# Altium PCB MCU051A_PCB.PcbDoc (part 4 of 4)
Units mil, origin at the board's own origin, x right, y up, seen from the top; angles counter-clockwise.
Board outline 4000 x 6000 mil, 6 copper layers (Top Layer, Signal Layer 1, Signal Layer 2, Signal Layer 3, Signal Layer 4, Bottom Layer), stack 60.4 mil thick; 193 components, 239 nets, 864 pads, 621 vias.
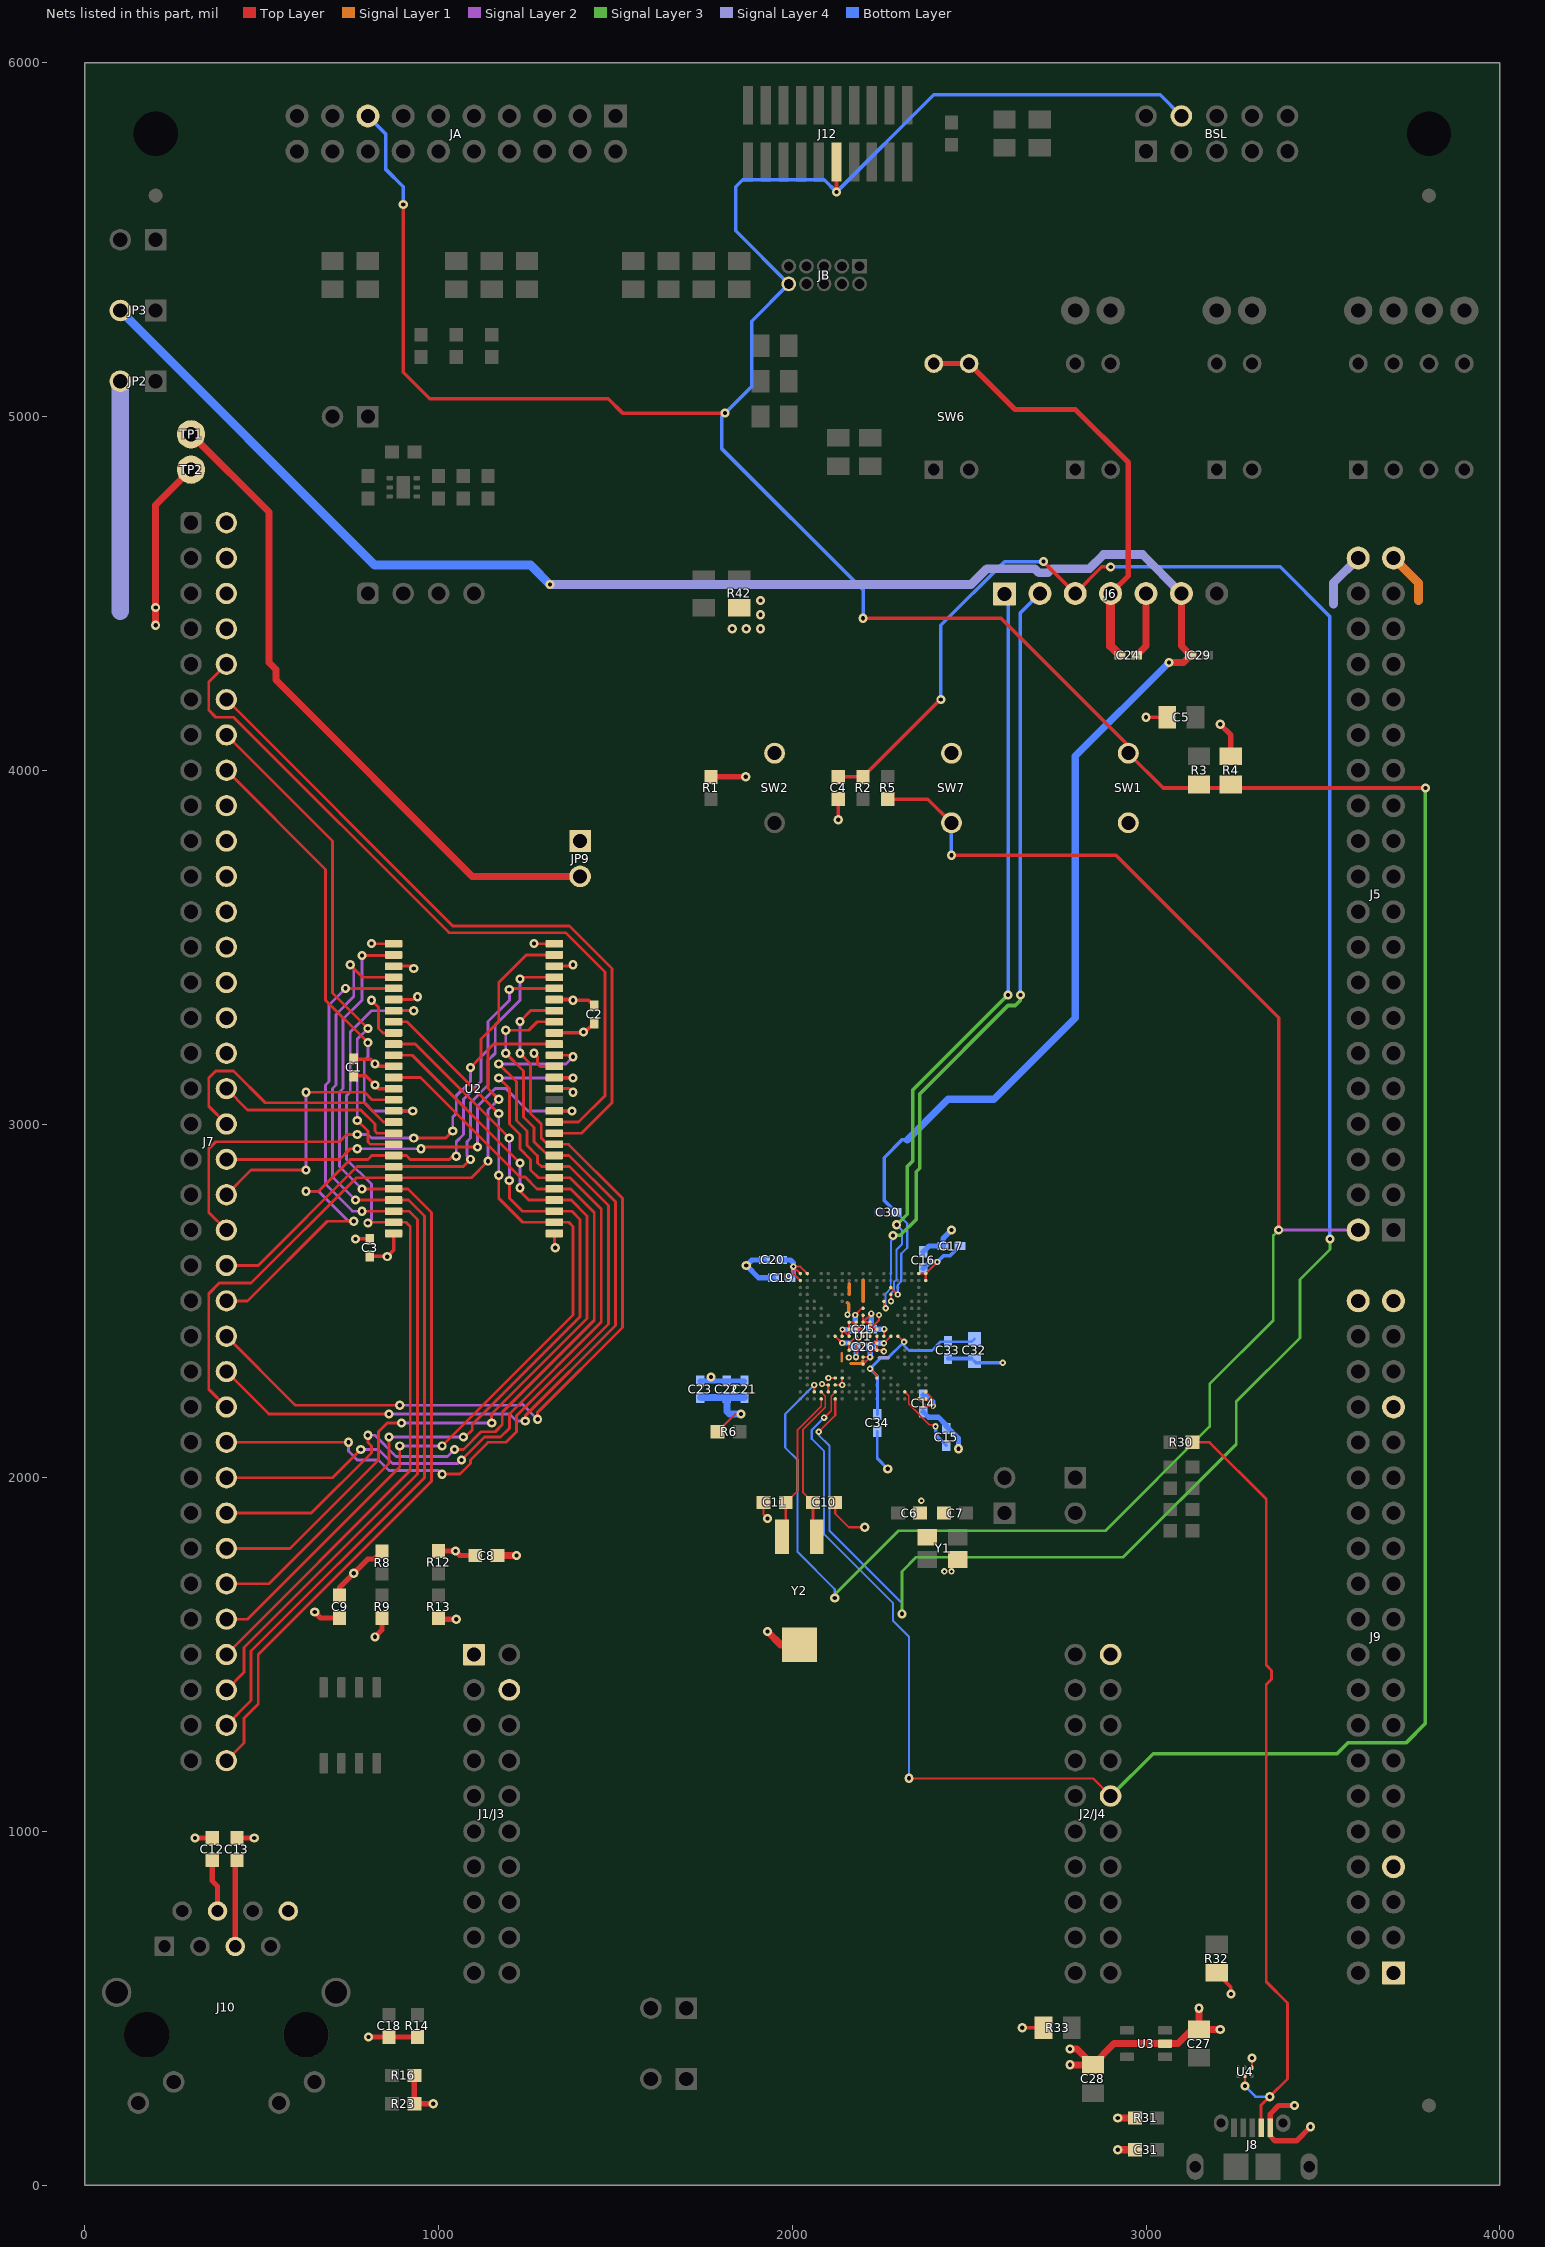
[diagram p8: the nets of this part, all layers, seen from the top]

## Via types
v1: diameter 26, hole 12, Top Layer to Bottom Layer, tented both sides, 517 vias
v2: diameter 18, hole 8, Top Layer to Bottom Layer, tented both sides, 94 vias
v3: diameter 26, hole 12, Top Layer to Bottom Layer, 7 vias
v4: diameter 19.68, hole 7.87, Top Layer to Bottom Layer, 2 vias
v5: diameter 18, hole 8, Top Layer to Bottom Layer, 1 vias

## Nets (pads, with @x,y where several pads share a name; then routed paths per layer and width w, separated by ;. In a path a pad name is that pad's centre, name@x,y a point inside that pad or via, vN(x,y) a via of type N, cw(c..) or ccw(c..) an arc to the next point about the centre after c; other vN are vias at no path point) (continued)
RSTn: BSL.4 J2/J4.16 J12.10 JA.15 JB.10 R3.1 R4.1 SW1.1 U1.P18 | length 12003
  Top Layer w4: v2(2090,2170) 2109.57,2189.57 2109.57,2230.83 U1.P18@2121.26,2242.52
  Top Layer w6: v1(2330,1150) 2850,1150 J2/J4.16@2900,1100
  Top Layer w10: v1(900,5600) 900,5125 975,5050 1480,5050 1520,5010 v1(1810,5010) ; v1(2125,5635) J12.10@2125,5719.88 ; v1(2200,4430) 2590,4430 2950,4070 SW1.1@2950,4048.43 3048.43,3950 v1(3790,3950)
  Signal Layer 3 w10: J2/J4.16@2900,1100 3020,1220 3540,1220 3570,1250 3735,1250 3790,1305 v1(3790,3950)
  Bottom Layer w6: v2(2090,2170) 2055,2135 2055,2110 2090,2075 2090,1840 2285,1645 2285,1595 2330,1550 v1(2330,1150)
  Bottom Layer w10: JA.15@800,5850 850,5800 850,5700 900,5650 v1(900,5600) ; v1(2200,4430) 2200,4510 1800,4910 1800,5000 v1(1810,5010) 1885,5085 1885,5270 JB.10@1990,5375 1840,5525 1840,5650 1860,5670 2090,5670 v1(2125,5635) 2400,5910 3040,5910 BSL.4@3100,5850
S00: J7.72 U2.2 U2.23 | length 2814.7
  Top Layer w8: J7.72@400,1200 450,1250 450,1320 490,1360 490,1500 980,1990 980,2750 913.46,2816.54 U2.23@872.64,2816.54 v1(783.46,2816.54) ; v1(783.46,3476.54) U2.2@871.22,3476.54
  Signal Layer 2 w8: v1(783.46,2816.54) 720,2880 720,3090 730,3100 730,3296.54 783.46,3350 v1(783.46,3476.54)
S01: J7.70 U2.4 U2.24 | length 2743.7
  Top Layer w8: J7.70@400,1300 470,1370 470,1510 960,2000 960,2740 914.96,2785.04 U2.24@872.64,2785.04 v1(764.96,2785.04) ; v1(750,3450) 785.04,3414.96 U2.4@872.64,3414.96
  Signal Layer 2 w8: v1(750,3450) 760,3440 760,3360 710,3310 710,3110 700,3100 700,2850 v1(764.96,2785.04)
S02: J7.68 U2.5 U2.25 | length 2568.1
  Top Layer w8: J7.68@400,1400 450,1450 450,1520 940,2010 940,2730 916.46,2753.54 U2.25@872.64,2753.54 v1(783.54,2753.54) ; v1(736.54,3383.46) U2.5@872.64,3383.46
  Signal Layer 2 w8: v1(736.54,3383.46) 690,3336.93 690,3120 680,3110 680,2830 756.46,2753.54 v1(783.54,2753.54)
S03: J7.66 U2.7 U2.26 | length 2390.9
  Top Layer w8: J7.66@400,1500 920,2020 920,2710 907.95,2722.05 U2.26@872.64,2722.05 802.05,2722.05 v1(800,2720) ; U2.7@872.64,3320.47 929.53,3320.47 v1(930,3320)
  Signal Layer 2 w8: v1(800,2720) 810,2730 810,2830 740,2900 740,3080 750,3090 750,3260 810,3320 v1(930,3320)
S04: J7.64 U2.8 U2.29 | length 2509.1
  Top Layer w8: J7.64@400,1600 460,1600 890,2030 v1(890,2090) ; U2.8@872.64,3288.98 911.02,3288.98 v1(1170,3030) ; v1(1010,2090) 1380,2460 1380,2710 1367.95,2722.05 U2.29@1327.36,2722.05 1237.95,2722.05 1170,2790 v1(1170,2855)
  Signal Layer 2 w8: v1(890,2090) v1(1010,2090) ; v1(1170,2855) v1(1170,3030)
S05: J7.62 U2.10 U2.30 | length 2477
  Top Layer w8: J7.62@400,1700 520,1700 860,2040 v1(860,2115) ; U2.10@872.64,3225.98 934.02,3225.98 v1(1200,2960) ; v1(1070,2115) 1075,2115 1095,2135 1095,2150 1400,2455 1400,2730 1376.46,2753.54 U2.30@1327.36,2753.54 1236.46,2753.54 1200,2790 v1(1200,2840)
  Signal Layer 2 w8: v1(860,2115) v1(1070,2115) ; v1(1200,2840) 1200,2950 1205,2955 v1(1200,2960)
S06: J7.60 U2.11 U2.31 | length 2435.3
  Top Layer w8: J7.60@400,1800 580,1800 830,2050 830,2130 855,2155 v1(895,2155) ; U2.11@872.64,3194.49 925.51,3194.49 v1(1230,2890) ; v1@1150,2150 v1(1150,2155) 1150,2180 1420,2450 1420,2740 1374.96,2785.04 U2.31@1327.36,2785.04 1254.96,2785.04 1230,2810 v1(1230,2820)
  Signal Layer 2 w8: v1(895,2155) v1@1145,2155 ; v1@1150,2150 v1@1145,2155 ; v1(1150,2155) v1@1145,2155 ; v1(1230,2820) v1(1230,2890)
S07: J7.58 U2.13 U2.32 | length 2409.8
  Top Layer w8: J7.58@400,1900 640,1900 810,2070 810,2090 800,2100 v1(800,2120) ; U2.13@872.64,3131.5 948.5,3131.5 1230,2850 1245,2850 1278.46,2816.54 U2.32@1327.36,2816.54 1373.46,2816.54 1440,2750 1440,2445 1180,2185 1180,2150 1160,2130 1120,2130 1070,2080 v1(1045,2080)
  Signal Layer 2 w8: v1(800,2120) 820,2120 880,2060 1025,2060 v1(1045,2080)
S08: J7.56 U2.33 U2.42 | length 2422.8
  Top Layer w8: J7.56@400,2000 700,2000 v1(780,2080) ; v1(1065,2050) 1130,2115 1175,2115 1200,2140 1200,2180 1460,2440 1460,2760 1371.97,2848.03 U2.33@1327.36,2848.03 1281.97,2848.03 1260,2870 1260,2900 1230,2930 1230,2970 1200,3000 1200,3100 v1(1170,3130) ; U2.42@1327.36,3131.5 v1@1378.5,3131.5
  Signal Layer 2 w8: v1(780,2080) 830,2080 870,2040 1055,2040 v1(1065,2050) ; v1(1170,3130) v1(1380,3130)
S09: J7.54 U2.34 U2.44 | length 2523.2
  Top Layer w8: J7.54@400,2100 v1(745,2100) ; v1(1010,2010) 1060,2010 1090,2040 1090,2050 1140,2100 1190,2100 1220,2130 1220,2175 1480,2435 1480,2770 1370.47,2879.53 U2.34@1327.36,2879.53 1290.47,2879.53 1280,2890 1280,2910 1250,2940 1250,2980 1220,3010 1220,3120 v1(1170,3170) ; U2.44@1327.36,3194.49 1375.51,3194.49 v1(1380,3190)
  Signal Layer 2 w8: v1(745,2100) 745,2075 770,2050 830,2050 860,2020 1000,2020 v1(1010,2010) ; v1(1170,3170) 1360,3170 v1(1380,3190)
S10: J7.52 U2.22 U2.45 | length 1819.9
  Top Layer w8: J7.52@400,2200 350,2250 350,2520 380,2550 470,2550 768.03,2848.03 U2.22@872.64,2848.03 1093.03,2848.03 v1(1140,2895) ; v1(1170,3070) 1140,3100 1140,3210 1155.98,3225.98 U2.45@1327.36,3225.98
  Signal Layer 2 w8: v1(1140,2895) 1140,3040 v1(1170,3070)
S11: J7.50 U2.35 U2.47 | length 2424.5
  Top Layer w8: J7.50@400,2300 520,2180 v1(860,2180) ; v1(1190,3200) 1240,3150 1240,3020 1270,2990 1270,2950 1308.98,2911.02 U2.35@1327.36,2911.02 1368.98,2911.02 1500,2780 1500,2430 1245,2175 v1(1245,2160) ; v1(1190,3265) 1255,3265 1278.98,3288.98 U2.47@1327.36,3288.98
  Signal Layer 2 w8: v1(860,2180) 1200,2180 1220,2160 v1(1245,2160) ; v1(1190,3200) v1(1190,3265)
S12: J7.48 U2.36 U2.48 | length 2471.1
  Top Layer w8: J7.48@400,2400 590,2210 595,2205 v1(890,2205) ; v1(1230,3200) 1260,3170 1260,3030 1290,3000 1290,2960 1307.48,2942.52 U2.36@1327.36,2942.52 1367.48,2942.52 1520,2790 1520,2425 1290,2195 1280,2185 v1(1280,2165) ; v1(1230,3290) 1260.47,3320.47 U2.48@1327.36,3320.47
  Signal Layer 2 w8: v1(890,2205) 1230,2205 1235,2210 v1(1280,2165) ; v1(1230,3200) v1(1230,3290)
S13: J7.46 U2.20 U2.50 | length 1761.9
  Top Layer w8: J7.46@400,2500 460,2500 685,2725 v1(760,2725) ; v1(625,2810) 660,2810 750,2900 800,2900 811.02,2911.02 U2.20@872.64,2911.02 908.98,2911.02 920,2900 1030,2900 1040,2910 1050,2910 v1(1050,2909) ; v1(1200,3380) 1203.46,3383.46 U2.50@1327.36,3383.46
  Signal Layer 2 w8: v1(625,2810) 660,2810 745,2725 v1(760,2725) ; v1(1050,2909) 1050,2950 1070,2970 1070,3070 1120,3120 1120,3190 1140,3210 1140,3290 1200,3350 v1(1200,3380)
S14: J7.44 U2.21 U2.51 | length 1490
  Top Layer w8: J7.44@400,2600 490,2600 769.53,2879.53 U2.21@872.64,2879.53 1069.53,2879.53 v1(1090,2900) ; v1(1230,3410) 1234.96,3414.96 U2.51@1327.36,3414.96
  Signal Layer 2 w8: v1(1090,2900) 1080,2910 1080,2950 1090,2960 1090,3060 1140,3110 1140,3180 1160,3200 1160,3280 1230,3350 v1(1230,3410)
S15: J7.42 U2.53 | length 1633.2
  Top Layer w8: J7.42@400,2700 350,2750 350,2930 370,2950 720,2950 740,2970 v1(770,2970) ; v1(930,2960) 1020,2960 v1(1040,2980) ; v1(1090,3160) 1120,3190 1120,3240 1170,3290 1170,3400 1247.95,3477.95 U2.53@1327.36,3477.95
  Signal Layer 2 w8: v1(770,2970) 800,2970 810,2960 v1(930,2960) ; v1(1040,2980) 1040,3020 1050,3030 1050,3080 1090,3120 v1(1090,3160)
S16: J7.40 U2.15 | length 730.5
  Top Layer w8: J7.40@400,2800 470,2870 v1(625,2870) ; v1(625,3090) 790,3090 811.5,3068.5 U2.15@872.64,3068.5
  Signal Layer 2 w8: v1(625,2870) 625,2895 v1(625,3090)
S17: J7.38 U2.39 | length 1203
  Top Layer w8: J7.38@400,2900 720,2900 750,2930 v1(770,2930) ; v1(950,2930) 955,2935 v1(1110,2935) ; U2.39@1327.36,3037.01 v1(1377.01,3037.01)
  Signal Layer 2 w8: v1(770,2930) v1(950,2930) ; v1(1110,2935) 1110,3050 1160,3100 1190,3100 1252.99,3037.01 v1(1377.01,3037.01)
S18: J7.36 U2.17 | length 741.5
  Top Layer w8: J7.36@400,3000 350,3050 350,3130 370,3150 420,3150 510,3060 790,3060 844.49,3005.51 U2.17@872.64,3005.51
S19: J7.34 U2.18 | length 536.5
  Top Layer w8: J7.34@400,3100 460,3040 780,3040 820,3000 820,2980 825.98,2974.02 U2.18@872.64,2974.02
S20: J7.32
S21: J7.30
S22: J7.28
S23: J7.26
S24: J7.24
S25: J7.22
S26: J7.20
S27: J7.18
S28: J7.16 U2.16 | length 1310.7
  Top Layer w8: J7.16@400,4000 680,3720 680,3350 v1(800,3230) ; U2.16@872.64,3037.01 v1(927.01,3037.01)
  Signal Layer 2 w8: v1(800,3230) 800,3190 790,3180 790,3060 812.99,3037.01 v1(927.01,3037.01)
S29: J7.14 U2.19 | length 1416.3
  Top Layer w8: J7.14@400,4100 700,3800 700,3370 v1(800,3270) ; v1(770,3010) 800,2980 800,2950 807.48,2942.52 U2.19@872.64,2942.52
  Signal Layer 2 w8: v1(770,3010) 770,3240 v1(800,3270)
S30: J7.12 U2.37 | length 1983.1
  Top Layer w8: J7.12@400,4200 1040,3560 1370,3560 1490,3440 1490,3060 1404.02,2974.02 U2.37@1327.36,2974.02
S31: J7.10 U2.38 | length 2100.7
  Top Layer w8: J7.10@400,4300 350,4250 350,4170 370,4150 420,4150 1029.06,3540.94 1359.06,3540.94 1470,3430 1470,3080 1395.51,3005.51 U2.38@1327.36,3005.51
S32: J7.8
S33: J7.6
S34: J7.4
S35: J7.2
TARGET_ID: J8.4 R30.2 U4.2 | length 2231.1
  Top Layer w6: v1(3280,280) U4.2@3280,308.19
  Top Layer w8: R30.2@3131.5,2100 3180,2100 3340,1940 3340,1470 3355,1455 3355,1430 3340,1415 3340,575 3400,515 3400,300 v1(3350,250) 3325.59,225.59 J8.4@3325.59,162.4
  Bottom Layer w8: v1(3280,280) 3310,250 v1(3350,250)
VBAT: C4.1 J6.3 R2.1 U1.P19 | length 6269.9
  Top Layer w6: v2(2075,2130) 2121.26,2176.26 U1.P19@2121.26,2222.83
  Top Layer w10: C4.1@2130,3981.5 R2.1@2200,3981.5 2418.5,4200 v1(2420,4200) ; v1(2710,4590) J6.3@2800,4500 2875,4575 v1(2900,4575)
  Signal Layer 3 w8: v1(2310,1615) 2310,1735 2350,1775 2935.43,1775 3255,2094.57 3255,2215 3435,2395 3435,2560 3520,2645 v1(3520,2675)
  Bottom Layer w6: 2075,2120 2105,2090 2105,1850 2310,1645 v1(2310,1615)
  Bottom Layer w10: v1(2420,4200) 2420,4410 2600,4590 v1(2710,4590) ; v1(2900,4575) 3380,4575 3520,4435 v1(3520,2675)
VDD: C8.1 C9.1 C12.1 C13.1 C14.2 C15.2 C16.2 C17.2 C19.2 C20.2 C21.2 C22.2 C23.2 C24.2 C25.2 C26.2 J1/J3.1 J5.40 J6.4 J9.1 J9.33 J10.4 J10.5 JP2.2 JP9.1 R1.2 R4.2 R8.2 R9.2 R12.2 R13.2 SW6.2 SW6.4 U1.G10 U1.H9 U1.J8 U1.J9 U1.J10 U1.K7 U1.K8 U1.K11 U1.K12 U1.L10 U1.L11 U1.L12 U1.M11 U1.M12 U1.N16 U1.P10 U1.P17 | length 4261.9
  Top Layer w6: U1.P17@2121.26,2262.2 v2@2140.8,2262.2 ; U1.P10@2121.26,2400 v2@2140.63,2380.63 ; v2@2140.94,2262.35 U1.N16@2140.94,2281.89 ; U1.M12@2160.63,2360.63 U1.M11@2160.63,2380.32 U1.L10@2180.32,2400 U1.K11@2200,2380.32 U1.K12@2200,2360.63 U1.L12@2180.32,2360.63 ; v2@2180.32,2341.32 U1.L12@2180.32,2360.63 ; U1.L11@2180.32,2380.32 U1.L12@2180.32,2360.63 ; U1.K7@2200,2459.06 U1.K8@2200,2440 ; U1.J10@2219.69,2400 U1.J9@2219.69,2419.69 ; v2(2223,2464) 2223,2463 U1.K8@2200,2440 ; U1.H9@2239.37,2419.69 U1.J9@2219.69,2419.69 ; v2(2245,2460) 2245,2445 U1.J9@2219.69,2419.69 ; U1.G10@2259.06,2400 v2@2259.06,2419.06 ; U1.K8@2200,2440 U1.K8@2200,2439.37 U1.J8@2219.69,2439.37 U1.J9@2219.69,2419.69
  Top Layer w15: C12.1@360,918.5 360,860 375,845 J10.4@375,774.8 ; J10.5@425,674.8 425,913.5 C13.1@430,918.5 ; C9.1@720,1666.5 720,1690 800,1770 818.5,1770 R8.2@840,1791.5 ; v1(820,1550) 840,1570 R9.2@840,1603.5 ; R12.2@1000,1792.52 v1(1047.48,1792.52) 1060,1780 C8.1@1103.5,1780 ; R13.2@1003.5,1600 v1(1050,1600) ; R1.2@1770,3981.5 v1(1868.5,3981.5) ; SW6.2@2400,5150 SW6.4@2500,5150 2630,5020 2800,5020 2950,4870 2950,4550 J6.4@2900,4500 ; v1(3210,4130) 3240,4100 R4.2@3240,4040
  Top Layer w25: J6.4@2900,4500 2900,4351.38 C24.2@2926.38,4325
  Signal Layer 4 w10: 2200,2498.43 2200,2557.48 ; 2246.5,2339.5 2247,2339 2266.46,2339 2266.96,2339.5 2271.5,2339.5
  Signal Layer 4 w25: 3530,4470 3530,4530 J5.40@3600,4600
  Signal Layer 4 w50: 100,4450 JP2.2@100,5100
  Bottom Layer w15: C23.2@1740,2273.62 C22.2@1815,2273.62 C21.2@1865,2273.62 ; C20.2@1921.38,2615.63 1885.63,2615.63 v1(1870,2600) 1905,2565 C19.2@1946.38,2565 ; v2(2141,2381) 2165.38,2381 C26.2@2176.38,2370 2180,2366.38 v2(2180,2341) ; v2(2223,2464) 2223,2420.31 2223.31,2420 v2(2260,2420) ; C16.2@2370,2638.62 2386.38,2655 C17.2@2426.38,2655 2426.38,2676.38 v1(2450,2700) ; C14.2@2370.32,2186.38 2385.69,2171 2413.21,2171 2435,2149.21 2435,2146.65 2470,2111.65 v1(2470,2082)
  other v1: 760,1730 1770,2285
  other v2: 2141,2262 2160,2340
VDD_SD: C1.2 C2.2 C3.2 JP9.2 TP1.1 U2.1 U2.3 U2.9 U2.14 U2.27 U2.43 U2.49 | length 2597.2
  Top Layer w8: v1(810,3350) 830,3330 830,3270 842.52,3257.48 U2.9@872.64,3257.48 ; v1@810.55,3509.45 U2.1@872.64,3509.45 ; U2.3@872.64,3446.46 923.54,3446.46 v1(930,3440) ; v1(1270,3200) 1280,3190 1280,3170 1287.01,3162.99 U2.43@1327.36,3162.99
  Top Layer w10: C1.2@760,3136.38 793.62,3136.38 830,3100 U2.14@872.64,3100 ; C3.2@805,2626.38 856.38,2626.38 872.64,2642.64 U2.27@872.64,2690.55 ; U2.49@1327.36,3351.97 1378.03,3351.97 v1(1380,3350) 1423.62,3350 C2.2@1440,3333.62
  Top Layer w20: TP1.1@300,4950 520,4730 520,4305 540,4285 540,4255 1095,3700 JP9.2@1400,3700
  other v1: 855,2625 820,3110 810,3510
VDDA: C29.2 C30.2 J6.6 JP3.2 U1.F3 | length 5938.2
  Top Layer w6: U1.F3@2278.74,2537.8 2278.74,2537.26 v2(2298,2518)
  Top Layer w20: v1(3065,4305) 3106.38,4305 C29.2@3126.38,4325 3100,4351.38 J6.6@3100,4500
  Signal Layer 4 w25: v1(1315,4525) 2505,4525 2510,4530 2550,4570 2685.45,4570 2696.95,4558.5 2723.05,4558.5 2734.55,4570 2840,4570 2880,4610 2990,4610 J6.6@3100,4500
  Bottom Layer w6: C30.2@2293.62,2750 2325,2718.62 2325,2650 2308,2633 2308,2555 2298,2545 v2(2298,2518)
  Bottom Layer w10: C30.2@2293.62,2750 2260,2783.62 2260,2905 2310,2955 2325,2955
  Bottom Layer w20: 2325,2955 2440,3070 2570,3070 2800,3300 2800,4040 v1(3065,4305)
  Bottom Layer w25: JP3.2@100,5300 820,4580 1260,4580 v1(1315,4525)
VDDC: C32.1 C33.2 C34.2 U1.E10 U1.H16 | length 552.4
  Top Layer w6: v2(2220,2308) 2239.37,2288.63 U1.H16@2239.37,2281.89 ; U1.E10@2298.43,2400 2300,2400 v2(2316,2384)
  Bottom Layer w8: v2(2220,2308) 2250,2338 2270,2338 v2(2316,2384) 2316,2374 2330,2360 2395,2360 2419.25,2384.25 C33.2@2440,2384.25 2507.13,2384.25 C32.1@2515,2392.13 ; v2(2220,2308) 2236,2292.04 ; 2236,2292 2241,2287 2241,2179.62 C34.2@2240,2178.62
VREFA+: J6.1 U1.F4 | length 2182.5
  Top Layer w6: v2@2278.74,2499.26 U1.F4@2278.74,2518.11
  Signal Layer 3 w10: v1(2295,2715) 2325,2745 2325,2880 2340,2895 2340,3095 v1(2610,3365)
  Bottom Layer w6: v2(2279,2499) 2279,2521.63 2288,2530.63 2288,2554 2295,2561 2295,2645 2310,2660 2310,2700 ; v1(2295,2715) 2310,2700 ; 2310,2690 2310,2700
  Bottom Layer w10: J6.1@2600,4499 2610,4489 v1(2610,3365)
VREFA-: J6.2 U1.G5 | length 2247.3
  Top Layer w6: U1.G5@2259.06,2498.43 2259.06,2483.94 v2(2264,2479)
  Signal Layer 3 w10: v1(2285,2685) 2305,2685 2350,2730 2350,2865 2360,2875 2360,3085 2610,3335 2630,3335 2645,3350 v1(2645,3365)
  Bottom Layer w4: 2264,2520.37 2278.74,2535.11 2278.74,2577.17
  Bottom Layer w6: v2(2264,2479) 2263,2480 2263,2506.63 2264,2507.63 2264,2520.37 ; 2278.74,2577.17 2278.74,2668.74 2285,2675 v1(2285,2685)
  Bottom Layer w10: v1(2645,3365) 2645,4445 J6.2@2700,4500
VSS: C1.1 C2.1 C3.1 C4.2 C5.1 C6.1 C7.1 C8.2 C9.2 C10.1 C11.1 C12.2 C13.2 C14.1 C15.1 C16.1 C17.1 C18.2 C19.1 C20.1 C21.1 C22.1 C23.1 C24.1 C25.1 C26.1 C27.2 C28.2 C31.2 C32.2 C33.1 C34.1 J1/J3.22 J2/J4.20 J5.39 J6.5 J8.5 J9.7 J9.39 J9.40 J10.8 R6.1 R14.1 R16.1 R23.1 R31.1 R32.2 R33.1 R42.2 SW1.2 SW2.1 SW7.1 TP2.1 U1.A1 U1.A2 U1.A18 U1.A19 U1.B1 U1.B19 U1.D18 U1.F10 U1.H10 U1.H11 U1.H12 U1.J11 U1.J12 U1.K6 U1.K9 U1.K10 U1.K13 U1.K14 U1.L8 U1.L9 U1.M8 U1.M9 U1.M10 U1.N10 U1.P16 U1.R17 U1.R18 U1.V1 U1.W1 U1.W2 U2.6 U2.12 U2.28 U2.41 U2.46 U2.52 U2.54 U3.2 U4.4 Y1.2 Y1.4 Y2.3 | length 5513.2
  Top Layer w4: U1.D18@2318.11,2242.52 2329.03,2231.6 2329.03,2208.7 2387.73,2150 2400,2150 v2(2405,2145)
  Top Layer w6: R6.1@1788.5,2130 1838.5,2180 v1(1855,2180) ; C11.1@1918.5,1930 1918.5,1896.5 v1(1930,1885) ; U1.W2@2022.83,2557.48 2003.15,2577.17 v2(2003.15,2596.85) ; U1.W1@2022.83,2577.17 v2(2003.15,2596.85) ; U1.V1@2042.52,2577.17 2022.83,2596.85 v2(2003.15,2596.85) ; v2(2084,2265) 2086.8,2262.2 U1.R17@2101.57,2262.2 U1.R18@2101.57,2242.52 ; v2@2102.11,2281.89 U1.P16@2121.26,2281.89 ; C10.1@2121.5,1930 2121.5,1898.5 2160,1860 v1(2205,1860) ; U1.N10@2140.94,2400 v2@2140.94,2417.94 ; v2@2142.69,2417.94 U1.M10@2160.63,2400 U1.M9@2160.63,2419.69 U1.M8@2160.63,2439.37 U1.L8@2180.32,2439.37 U1.L9@2180.32,2419.69 U1.K9@2200,2419.69 U1.K10@2200,2400 ; v2(2178,2460) 2196.74,2478.74 U1.K6@2200,2478.74 ; U1.K14@2200,2321.26 2200.26,2321.26 v2@2219.94,2340.94 ; U1.K13@2200,2340.94 v2@2219.94,2340.94 ; U1.J11@2219.69,2380.32 U1.H11@2239.37,2380.32 ; U1.H10@2239.37,2400 U1.H11@2239.37,2380.32 ; 2250.37,2360.63 U1.H12@2239.37,2360.63 ; v2@2258.68,2380.32 2278.37,2400 U1.F10@2278.74,2400 ; U1.B19@2357.48,2222.83 2377.17,2203.15 v2(2396.85,2203.15) ; U1.B1@2357.48,2577.17 U1.A1@2377.17,2577.17 ; U1.A19@2377.17,2222.83 v2(2396.85,2203.15) ; U1.A18@2377.17,2242.52 2396.85,2222.83 v2(2396.85,2203.15) ; U1.A2@2377.17,2557.48 U1.A1@2377.17,2577.17 ; v2(2410,2610) U1.A1@2377.17,2577.17 ; U4.4@3299.68,331.81 v1(3299.68,359.68) ; v2@2219.94,2340.94 v2(2220,2341) 2220,2360.32 U1.J12@2219.69,2360.63 U1.H12@2239.37,2360.63 ; U1.H12@2239.37,2360.63 U1.H11@2239.37,2380.32
  Top Layer w8: U2.6@872.64,3351.97 928.03,3351.97 ; v1@1270.55,3509.45 U2.54@1327.36,3509.45 ; v1@1327.36,2652.64 U2.28@1327.36,2690.55 ; U2.41@1327.36,3100 1370,3100 ; U2.52@1327.36,3446.46 v1@1376.46,3446.46
  Top Layer w10: C1.1@760,3183.62 806.38,3183.62 827.01,3162.99 U2.12@872.64,3162.99 ; v1(765,2675) C3.1@803.62,2675 ; U2.46@1327.36,3257.48 1411.1,3257.48 C2.1@1440,3286.38 ; v1(2130,3860) C4.2@2130,3918.5 ; v1(2650,445) 2705,445 R33.1@2710,450 ; v1(3000,4150) C5.1@3060,4150 ; R32.2@3200,600 3240,560 v1(3240,540)
  Top Layer w15: v1(311.5,981.5) C12.2@360,981.5 ; C13.2@430,981.5 v1(478.5,981.5) ; v1(650,1620) 666.5,1603.5 C9.2@720,1603.5 ; v1(801.5,418.5) R14.1@940,418.5 ; R16.1@931.5,310 R23.1@931.5,230 v1(985,230) ; v1(3420,225) 3375,225 3351.18,201.18 J8.5@3351.18,162.4 3351.18,138.82 3365,125 3425,125 v1(3465,165)
  Top Layer w20: v1(200,4410) v1(200,4460) 200,4750 TP2.1@300,4850 ; C8.2@1166.5,1780 v1(1220,1780) ; v1(1930,1565) 1967.24,1527.76 Y2.3@2020,1527.76 ; v1(2785,340) C28.2@2850,340 ; v1(2785,385) 2805,385 C28.2@2850,340 ; v1(2920,100) C31.2@2968.5,100 ; v1(2920,190) R31.1@2968.5,190 ; C24.1@2973.62,4325 3000,4351.38 J6.5@3000,4500 ; v1(3150,500) C27.2@3150,440 ; v1(3210,440) C27.2@3150,440 ; C28.2@2850,340 2910,400 U3.2@3054.13,400 3090,400 3130,440 C27.2@3150,440
  Signal Layer 1 w8: 2140,2330 2140,2351 ; 2165,2323 2192.5,2323 2200,2330.5
  Signal Layer 1 w10: 2156,2495 2160,2491 2160,2470 ; 2160.63,2518.11 2160.63,2548.85 ; 2200,2498.43 2200,2557.48
  Signal Layer 1 w25: J5.39@3700,4600 3770,4530 3770,4480
  Bottom Layer w8: C34.1@2240,2131.38 2240,2055 v1(2270,2025)
  Bottom Layer w10: v2(2405,2145) 2405,2123.35 2410,2118.35 2410,2116.38 C15.1@2435,2091.38 ; v2(2410,2610) 2427,2627 2445.62,2627 C17.1@2473.62,2655 ; C33.1@2440,2337.01 C32.2@2507.13,2337.01 ; C32.2@2515,2329.13 2519.13,2325 v5(2595,2325)
  Bottom Layer w15: C20.1@1968.62,2615.63 1994.37,2615.63 2003.15,2606.85 v2(2003.15,2596.85) 2003.15,2574.53 C19.1@1993.62,2565 ; v2(2142,2419) 2175.69,2419 C25.1@2176.38,2419.69 2178,2421.31 v2(2178,2460) ; v2(2220,2341) 2220,2366.38 C26.1@2223.62,2370 2233.62,2380 v2(2259,2380) ; C16.1@2370,2591.38 2388.62,2610 v2(2410,2610) ; C14.1@2370.32,2233.62 2378.23,2233.62 2396.85,2215 v2(2396.85,2203.15)
  Bottom Layer w20: C23.1@1740,2226.38 C22.1@1815,2226.38 ; v1(1855,2180) 1822.78,2180 1815,2187.78 C22.1@1815,2226.38 ; C21.1@1865,2226.38 C22.1@1815,2226.38
  other v1: 1330,2650 1380,3090 820,3170 1410,3260 940,3360 1380,3450 1270,3510 1830,4400 1870,4400 1910,4400 1910,4440 1910,4480
  other v2: 2430,1735 2450,1735 2365,1935 2102,2282 2259,2357 2156,2461
WAKE: J5.2 R5.1 SW7.2 U1.U18 | length 4855.6
  Top Layer w6: U1.U18@2062.2,2242.52 v2@2062.2,2261.8
  Top Layer w10: R5.1@2270,3918.5 2383.07,3918.5 SW7.2@2450,3851.57 ; v1(2450,3760) 2915,3760 3375,3300 v1(3375,2700)
  Signal Layer 2 w8: v1(3375,2700) J5.2@3600,2700
  Signal Layer 3 w8: v1(2120,1660) 2120,1670 2300,1850 2885,1850 3180,2145 3180,2265 3360,2445 3360,2685 v1(3375,2700)
  Bottom Layer w6: v2(2062,2262) 1980,2180 1980,2085 2015,2050 2015,1790 2120,1685 v1(2120,1660)
  Bottom Layer w10: v1(2450,3760) SW7.2@2450,3851.57
XOSC0: C10.2 U1.T18 Y2.2 | length 457.1
  Top Layer w4: 2030,2135 2093.57,2198.57 2093.57,2230.83 U1.T18@2081.89,2242.52
  Top Layer w6: 2030,2135 2030,1958.5 C10.2@2058.5,1930
  Top Layer w8: C10.2@2058.5,1930 2058.5,1843.58 Y2.2@2069.21,1832.87
XOSC1: C11.2 U1.T19 Y2.1 | length 436
  Top Layer w4: 2015,2135 2081.89,2201.89 U1.T19@2081.89,2222.83
  Top Layer w6: C11.2@1981.5,1930 2015,1963.5 2015,2135
  Top Layer w8: Y2.1@1970.79,1832.87 1981.5,1843.58 C11.2@1981.5,1930
pads on no net: BSL.2 BSL.7 FID1.1 FID2.1 FID3.1 FID4.1 FID5.1 FID6.1 H1.0 H2.0 J10.7 J10.MH1 J10.MH2 J12.7 JA.2 JA.3 MH1.1 MH2.1 SH-J7-1.0 SH-J7-2.0 SH-J7-3.0 SH-J7-4.0 SH-J7-5.0 SH-J7-6.0 SH-J7-7.0 SH-J7-8.0 SH-J7-9.0 SH-J7-10.0 SH-J7-11.0 SH-J7-12.0 SH-J7-13.0 SH-J7-14.0 SH-J7-15.0 SH-J7-16.0 SH-J7-17.0 SH-J7-18.0 SH-J7-19.0 SH-J7-20.0 SH-J7-21.0 SH-J7-22.0 SH-J7-23.0 SH-J7-24.0 SH-J7-25.0 SH-J7-26.0 SH-J7-27.0 SH-J7-28.0 SH-J7-29.0 SH-J7-30.0 SH-J7-31.0 SH-J7-32.0 SH-J7-33.0 SH-J7-34.0 SH-J7-35.0 SH-J7-36.0 SH-JP1.0 SH-JP2.0 SH-JP3.0 SH-JP4.0 SH-JP5.0 SH-JP6.0 SH-JP7.0 SH-JP8.0 SH-JP9.0 U1.C5 U1.E13 U1.V18 U1.V19 U1.W18 U1.W19 U2.40 U4.5 U5.7@900,4782.28 U5.7@900,4817.72

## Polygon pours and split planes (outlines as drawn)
VSS on Signal Layer 1 "VSS" (solid, remove dead copper, pour order 2): 0,4490 4000,4490 4000,0 0,0
GND on Signal Layer 1 "GND" (solid, remove dead copper, pour order 6): 0,6000 4000,6000 4000,4510 0,4510
VDD on Signal Layer 4 "VDD" (solid, remove dead copper, pour order 4): 0,4490 4000,4490 4000,0 0,0
VDD_SD on Signal Layer 4 "VDD_SD" (solid, remove dead copper, pour order 0): 700,3750 1500,3750 1500,2550 700,2550
3V3 on Signal Layer 4 "3V3" (solid, remove dead copper, pour order 8): 0,6000 4000,6000 4000,4510 0,4510
VSS on Top Layer "Top_VSS" (solid, remove dead copper, pour order 10): 1800,4490 1930,4490 1930,4380 1800,4380
GND on Top Layer "Top_GND" (solid, remove dead copper, pour order 12): 1930,4510 1930,4620 1670,4620 1670,4510
VSS on Top Layer "Y1_Top_VSS" (solid, remove dead copper, pour order 14): 2335,1945 2340,1805 2420,1725 2500,1725 2500,1945

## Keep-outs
Keep-Out Layer:
  text ".Layer_Name" at 577,-858.49 h60

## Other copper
Top Layer:
  region net VDD: 2141,2381 2161,2381 2180,2400 2200,2380 2200,2360 2180,2340 2153,2340 2141,2352
  region net VSS: 2220,2380 2220,2360 2200,2340 2200,2321 2206,2327 2234,2327 2259,2352 2259,2380
  region net VDD: 2246,2464 2200,2464 2200,2439 2220,2419 2260,2419 2260,2450
  region net VSS: 2150,2460 2180,2460 2180,2419 2160,2399 2141,2399 2141,2451
  text ".Layer_Name" at 577,-858.49 h60
Signal Layer 2:
  text ".Layer_Name" at 577,-858.49 h60
Signal Layer 3:
  text ".Layer_Name" at 577,-858.49 h60
Signal Layer 1:
  text ".Layer_Name" at 577,-858.49 h60
Signal Layer 4:
  text ".Layer_Name" at 577,-858.49 h60
Bottom Layer:
  text ".Layer_Name" at 577,-858.49 h60

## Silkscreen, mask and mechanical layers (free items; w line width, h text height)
Top Overlay:
  text "VDD+" at 275,5505 h60
  text "BSL - Select One" at 2860,5505 h60
  text "I2C" at 2375,5475 h60
  text "VDDA" at 275,5430 h60
  text "I2C" at 2775,5415 h60
  text "UART" at 3145,5415 h60
  text "SPI" at 3680,5415 h60
  text "Pullup" at 2290,5375 h60
  text "Enable" at 2290,5275 h60
  text "VDDA" at 275,5270 h60
  text "VDD" at 275,5070 h60
  text "VDD_SD" at 15,4930 h40
  text "GND" at 135,4830 h40
  text "PN5" at 125,4680 h40
  text "VREF" at 2575,4680 h40
  text "PN4" at 125,4580 h40
  text "3.3V" at 820,4570 h40 r90
  text "GND" at 920,4570 h40 r90
  text "GND" at 1020,4570 h40 r90
  text "5V" at 1120,4570 h40 r90
  text "A+" at 2620,4570 h40 r90
  text "A-" at 2720,4570 h40 r90
  text "VBAT" at 2820,4570 h40 r90
  text "VDD" at 2920,4570 h40 r90
  text "VSS" at 3020,4570 h40 r90
  text "VDDA" at 3120,4570 h40 r90
  text "AVSS" at 3220,4570 h40 r90
  text "PL5" at 125,4480 h40
  text "PD6" at 3425,4480 h40
  text "PG6" at 3770,4480 h40
  text "PK4" at 125,4380 h40
  text "PQ5" at 3425,4380 h40
  text "PM5" at 3770,4380 h40
  text "PK5" at 125,4280 h40
  text "PG2" at 3425,4280 h40
  text "PA1" at 3770,4280 h40
  text "PN3" at 125,4180 h40
  text "PA0" at 3425,4180 h40
  text "PF3" at 3770,4180 h40
  text "PP2" at 125,4080 h40
  text "PF4" at 3425,4080 h40
  text "PF2" at 3770,4080 h40
  text "PB3" at 125,3980 h40
  text "PF0" at 3425,3980 h40
  text "PF1" at 3770,3980 h40
  text "PB2" at 125,3880 h40
  text "PC0" at 3425,3880 h40
  text "PQ7" at 3770,3880 h40
  text "PL4" at 125,3780 h40
  text "PG7" at 3425,3780 h40
  text "PQ6" at 3770,3780 h40
  text "PJ0" at 1895,3760 h40
  text "WAKE" at 2375,3760 h40
  text "RESET" at 2855,3760 h40
  text "VDD / SD" at 1460,3685 h40
  text "PK6" at 125,3680 h40
  text "PN2" at 3425,3680 h40
  text "PN1" at 3770,3680 h40
  text "PK7" at 125,3580 h40
  text "PQ4" at 3425,3580 h40
  text "PS2" at 3770,3580 h40
  text "PQ3" at 125,3480 h40
  text "PB1" at 3425,3480 h40
  text "PB0" at 3770,3480 h40
  text "'.PRJ_Title'" at 2130,3390 h60
  text "PQ2" at 125,3380 h40
  text "PL6" at 3425,3380 h40
  text "PC2" at 3770,3380 h40
  text "PCB Rev '.PCB_Rev'" at 2130,3320 h40
  text "PQ1" at 125,3280 h40
  text "PL7" at 3425,3280 h40
  text "PC3" at 3770,3280 h40
  text "PQ0" at 125,3180 h40
  text "PC1" at 3425,3180 h40
  text "PN0" at 3770,3180 h40
  text "PL3" at 125,3080 h40
  text "PF5" at 3425,3080 h40
  text "PJ0" at 3770,3080 h40
  text "PL2" at 125,2980 h40
  text "PJ1" at 3425,2980 h40
  text "PH3" at 3770,2980 h40
  text "PL1" at 125,2885 h40
  text "PG3" at 3425,2880 h40
  text "PG4" at 3770,2880 h40
  text "PL0" at 125,2780 h40
  text "PG5" at 3425,2780 h40
  text "PD7" at 3770,2780 h40
  text "PM0" at 125,2680 h40
  text "WAKE" at 3385,2680 h40
  text "HIB" at 3770,2680 h40
  text "PM1" at 125,2580 h40
  text "PM2" at 125,2480 h40
  text "VSS" at 3425,2480 h40
  text "VSS" at 3770,2480 h40
  text "PM3" at 125,2380 h40
  text "PE7" at 3425,2380 h40
  text "PE6" at 3770,2380 h40
  text "PG0" at 125,2280 h40
  text "PP6" at 3425,2280 h40
  text "PP7" at 3770,2280 h40
  text "PG1" at 125,2180 h40
  text "5V" at 3425,2180 h40
  text "VDD" at 3770,2180 h40
  text "PA7" at 125,2080 h40
  text "PS3" at 3425,2080 h40
  text "PB4" at 3770,2080 h40
  text "PA6" at 125,1980 h40
  text "PS1" at 3425,1980 h40
  text "PS0" at 3770,1980 h40
  text "PT2" at 3770,1885 h40
  text "PC4" at 125,1880 h40
  text "PT3" at 3425,1880 h40
  text "PC5" at 125,1780 h40
  text "PJ5" at 3425,1780 h40
  text "PJ4" at 3770,1780 h40
  text "PC6" at 125,1680 h40
  text "PJ3" at 3425,1680 h40
  text "PJ2" at 3770,1680 h40
  text "PC7" at 125,1580 h40
  text "PN6" at 3425,1580 h40
  text "PN7" at 3770,1580 h40
  text "PK3" at 125,1480 h40
  text "PA2" at 2625,1480 h40
  text "PT1" at 3425,1480 h40
  text "PT0" at 3770,1480 h40
  text "PH2" at 125,1380 h40
  text "PE1" at 925,1380 h40
  text "PA3" at 2625,1380 h40
  text "PM7" at 2970,1380 h40
  text "PS7" at 3425,1380 h40
  text "PS6" at 3770,1380 h40
  text "PH1" at 125,1280 h40
  text "PP0" at 925,1280 h40
  text "PE5" at 1270,1280 h40
  text "PA4" at 2625,1280 h40
  text "PP5" at 2970,1280 h40
  text "PS5" at 3425,1280 h40
  text "PS4" at 3770,1280 h40
  text "PH0" at 125,1180 h40
  text "PP1" at 925,1180 h40
  text "PB5" at 1270,1180 h40
  text "PA5" at 2625,1180 h40
  text "PH7" at 2970,1180 h40
  text "PR7" at 3425,1180 h40
  text "PR6" at 3770,1180 h40
  text "Limited BoosterPack support" at 1485,1110 h40
  text "PH4" at 925,1080 h40
  text "PK0" at 1270,1080 h40
  text "PD4" at 2625,1080 h40
  text "RST" at 2970,1080 h40
  text "PR3" at 3425,1080 h40
  text "PF7" at 3770,1080 h40
  text "For a full list see" at 1645,1040 h40
  text "PE4" at 925,980 h40
  text "PK1" at 1270,980 h40
  text "PD5" at 2625,980 h40
  text "PD1" at 2970,980 h40
  text "PR5" at 3425,980 h40
  text "PR4" at 3770,980 h40
  text "ti.com/tool/MSP432E411Y-BGAEVM" at 1440,970 h40
  text "PD3" at 925,880 h40
  text "PK2" at 1270,880 h40
  text "PJ7" at 2625,880 h40
  text "PD0" at 2970,880 h40
  text "PJ6" at 3425,880 h40
  text "VSS" at 3770,880 h40
  text "PP4" at 925,780 h40
  text "PE0" at 1270,780 h40
  text "PM4" at 2625,780 h40
  text "PP3" at 2970,780 h40
  text "PR2" at 3425,780 h40
  text "PR0" at 3770,780 h40
  text "PB6" at 925,680 h40
  text "PH5" at 1270,680 h40
  text "PE2" at 2625,680 h40
  text "PD2" at 2970,680 h40
  text "PF6" at 3425,680 h40
  text "PR1" at 3770,680 h40
  text "PB7" at 925,580 h40
  text "PH6" at 1270,580 h40
  text "PE3" at 2625,580 h40
  text "PM6" at 2970,580 h40
  text "5V" at 3425,580 h40
  text "VDD" at 3770,580 h40
  text "'.PRJ_Number'.PCB_Rev" at 800,45 h40
  text ".Layer_Name" at 577,-858.49 h60
Bottom Overlay:
  text ".Layer_Name" at 577,-858.49 h60
Top Paste:
  text ".Layer_Name" at 577,-858.49 h60
Bottom Paste:
  text ".Layer_Name" at 577,-858.49 h60
Top Solder:
  text ".Layer_Name" at 577,-858.49 h60
  text ".Layer_Name" at 577,-858.49 h60
Bottom Solder:
  text ".Layer_Name" at 577,-858.49 h60
Drill Guide:
  text ".Layer_Name" at 577,-858.49 h60
M1 Board Outline:
  the board outline again, w10
  text ".Layer_Name" at 577,-858.49 h60
M2 Board Dimensions:
  rectangle: 0,-275 125,-150
  rectangle: 125,-400 500,-275
  lines w7: 0,-275 1000,-275 ; 125,-400 125,-150 ; 250,-400 250,-150 ; 500,-400 500,-150 ; 750,-400 750,-150 ; 0,-400 1000,-400 1000,-150 0,-150 0,-400
  text ".Layer_Name" at 577,-858.49 h60
M3 3D STEP Top:
  text ".Layer_Name" at 577,-858.49 h60
M4 3D STEP Bottom:
  text ".Layer_Name" at 577,-858.49 h60
M5 Assembly Top:
  lines w10: -292,-930.17 6308,-930.17 ; -292,-726.83 6310,-726.83 ; -292,-523.5 -292,-1133.5 3713,-1133.5 6310,-1133.5 6310,-523.5 -291.5,-523.5 -291.5,-1133.5 1284,-1133.5 ; 2173,-1133.5 2173,-523.5 ; 3440,-726.83 3440,-523.5 ; 4280,-726.83 4280,-523.5 ; 4902,-1140 4902,-937.17
  text "COMPONENTS MARKED 'DNP' SHOULD NOT BE POPULATED." at 1153.5,-318.5 h60
  text "ASSEMBLY VARIANT:" at 1153,-434 h60
  text ".VariantName" at 2189,-434 h60
  text "PCB VIEWED FROM TOP SIDE" at -228.5,-655.67 h60
  text "BOARD #:" at 2248,-655.67 h60
  text ".PRJ_Number" at 2793.5,-655.67 h60
  text "REV:" at 3638,-655.67 h60
  text ".PCB_Rev" at 3929.5,-655.67 h60
  text "SVN REV:" at 4476,-655.67 h60
  text ".VersionControl_RevNumber" at 4982,-655.67 h60
  text "TID #:" at 2248,-859 h60
  text ".TID" at 2793.5,-859 h60
  text "PLOT NAME =" at -228.5,-1064.34 h60
  text ".plot_File_Name" at 577,-1064.34 h60
  text "GENERATED    :" at 2250,-1064.34 h60
  text ".Print_Date" at 3119.5,-1064.34 h60
  text ".Print_Time" at 3848.5,-1064.34 h60
  text "TEXAS INSTRUMENTS" at 5113,-1064.34 h60
M6 Assembly Bottom:
  lines w10: -292.5,-727.33 6309.5,-727.33 ; -290.5,-930.67 6309.5,-930.67 ; 1115.5,-1140.5 1115.5,-937.67 ; 1737.5,-727.33 1737.5,-524 ; 2577.5,-727.33 2577.5,-524 ; 3844.5,-1134 3844.5,-524 ; 4733.5,-1134 6309,-1134 6309,-524 -292.5,-524 -292.5,-1134 2304.5,-1134 6309.5,-1134 6309.5,-524
  text "COMPONENTS MARKED 'DNP' SHOULD NOT BE POPULATED." at 6102,-318 h60
  text ".VariantName" at 5058,-434 h60
  text "ASSEMBLY VARIANT:" at 6097,-434 h60
  text ".VersionControl_RevNumber" at 1035.5,-656.17 h60
  text "SVN REV:" at 1541.5,-656.17 h60
  text ".PCB_Rev" at 2088,-656.17 h60
  text "REV:" at 2379.5,-656.17 h60
  text ".PRJ_Number" at 3224,-656.17 h60
  text "BOARD #:" at 3769.5,-656.17 h60
  text "PCB VIEWED FROM BOTTOM SIDE" at 6246,-656.17 h60
  text ".TID" at 3224,-859.5 h60
  text "TID #:" at 3769.5,-859.5 h60
  text "TEXAS INSTRUMENTS" at 904.5,-1064.84 h60
  text ".Print_Time" at 2169,-1064.84 h60
  text ".Print_Date" at 2898,-1064.84 h60
  text "GENERATED    :" at 3767.5,-1064.84 h60
  text ".plot_File_Name" at 5440.5,-1064.84 h60
  text "PLOT NAME =" at 6246,-1064.84 h60
M9 Title Sheet:
  drawing of 57 lines, arcs and shapes, not listed
  text "1" at 739.84,8036.5 h70
  text "2" at 3235.5,8036.5 h70
  text "3" at 5724.84,8036.5 h70
  text "4" at 8231.51,8036.5 h70
  text "5" at 10730.5,8036.5 h70
  text "6" at 13235.5,8036.5 h70
  text "A" at -416.5,6893.5 h70
  text "A" at 14383.5,6893.5 h70
  text "B" at -416.5,4513.5 h70
  text "B" at 14383.5,4513.5 h70
  text "C" at -416.5,2138.5 h70
  text "C" at 14383.5,2138.5 h70
  text "PROJECT TITLE:" at 11343.5,277.5 h45
  text ".PRJ_Title" at 11393.5,144.17 h70
  text "DESIGNED FOR:" at 11343.5,-23.5 h45
  text ".PRJ_Customer" at 11393.5,-163.5 h70
  text "D" at -416.5,-231.5 h70
  text "D" at 14383.5,-231.5 h70
  text "FILE NAME:" at 11343.5,-323.5 h45
  text ".PCB_File_Name_No_Path" at 11393.5,-443.5 h70
  text "Texas Instruments (TI) and/or its licensors do not warrant the accuracy or completeness of this specification" at 6374,-605.34 h45
  text "ENGINEER:" at 11343.5,-613.5 h45
  text "LAYOUT BY:" at 12848.5,-613.5 h45
  text "or any information contained therein. TI and/or its licensors do not warrant that this design will meet" at 6329.01,-718 h45
  text ".PRJ_Engineer" at 11393.5,-768.49 h70
  text ".PCB_Layout" at 12899,-768.49 h70
  text "the specifications, will be suitable for your application or fit for any particular purpose, or will operate in" at 6329.01,-830.67 h45
  text ".Layer_Name" at 577,-858.49 h60
  text "ALTIUM DESIGNER VERSION:" at 12848.5,-923.5 h45
  text "an implementation. TI and/or its licensors do not warrant that the design is production worthy. You should" at 6329.01,-943.33 h45
  text "completely validate and test your design implementation to confirm the system functionality for your application." at 6374,-1056 h45
  text ".print_Scale" at 11393.5,-1056.83 h70
  text ".Application_BuildNumber" at 12899,-1056.83 h70
  text "1" at 739.84,-1263.5 h70
  text "2" at 3235.5,-1263.5 h70
  text "3" at 5724.84,-1263.5 h70
  text "4" at 8231.51,-1263.5 h70
  text "5" at 10730.5,-1263.5 h70
  text "6" at 13235.5,-1263.5 h70
M10 Fab Notes:
  drawing of 189 lines, arcs and shapes, not listed
  text "DESIGN INFORMATION" at 12382.02,6356.17 h60
  text "MIN. TRACK WIDTH:" at 11737.46,6224.05 h60
  text "4" at 12833.7,6224.05 h60
  text "MIL" at 12988.46,6224.05 h60
  text "MIN. CLEARANCE:" at 11737.46,6099.92 h60
  text "4" at 12835,6100 h60
  text "MIL" at 12988.46,6099.92 h60
  text "MIN. VIA PAD SIZE:" at 11737.46,5975.8 h60
  text "18" at 12803.71,5975.8 h60
  text "MIL" at 12988.46,5975.8 h60
  text "0.05mm (2MIL)" at 12432.46,5845.9 h60
  text "MINIMUM ANNULAR RING" at 11408.23,5837.67 h60
  text "EXTERNAL" at 13140.46,5837.67 h60
  text "PER" at 11608.23,5727.55 h60
  text "IPC-D-275 CLASS 2 LEVEL C" at 11828.23,5727.54 h60
  text "MIL, HOLES" at 13316.46,5627.07 h60
  text "+/-" at 12924,5618.48 h60
  text "+/-" at 13778,5618.48 h60
  text "REGISTRATION TOLERANCES:" at 11408.23,5617.42 h60
  text "METAL" at 12608,5617.42 h60
  text "5" at 13184.2,5617.42 h60
  text "3" at 14017.2,5617.42 h60
  text "MIL" at 14133.46,5617.42 h60
  text "HOLE SIZE TOLERANCE (UNLESS OTHERWISE SPECIFIED):" at 11408.23,5519.1 h60
  text "+/-" at 13778,5516.23 h60
  text "3" at 14017.2,5515.17 h60
  text "MIL" at 14133.46,5515.17 h60
  text "MATERIAL:" at 11333.46,5377.52 h60
  text "FR-4 High Tg" at 12319.9,5249 h60
  text "X" at 12175.46,5241.01 h60
  text "FR-408" at 11754.46,5236.49 h60
  text "OTHER" at 13242.46,5236.49 h60
  text "62 MIL (1.6mm) +/-10%" at 12074.56,5093.46 h60
  text "X" at 11954.46,5091.01 h60
  text "THICKNESS:" at 11408.23,5085.24 h60
  text "OTHER" at 13359.46,5085.24 h60
  text "TOLERANCE:" at 11408.23,4946.92 h60
  text "X" at 12256.46,4946.92 h60
  text "ANSI IPC-6012 TYPE 3 CLASS 2" at 12434.48,4946.92 h60
  text "OTHER +/-" at 12434.46,4802.73 h60
  text "BOW & TWIST:" at 11408.23,4657.54 h60
  text "X" at 12256.46,4657.54 h60
  text "ANSI IPC-6012 TYPE 3 CLASS 2" at 12434.48,4657.54 h60
  text "OTHER +/-" at 12434.46,4510.85 h60
  text "DRILLING:" at 11333.46,4380.23 h60
  text "NC_DRILL FILES" at 13094.46,4275.04 h60
  text "REFERENCE:" at 11408.23,4271.1 h60
  text "X" at 12065.46,4271.01 h60
  text "AS SHOWN" at 12243.46,4271.1 h60
  text "X" at 12966.46,4271.1 h60
  text "OTHER" at 13392.46,4128.85 h60
  text "PTH COPPER THICKNESS:" at 11407.91,4125.32 h60
  text "X" at 12547.14,4125.32 h60
  text "20-30 um" at 12675.14,4125.32 h60
  text "BOARD FINISH:" at 11333.46,3977.73 h60
  text "SILKSCREEN:" at 11488.68,3867.6 h60
  text "X" at 12446.46,3867.6 h60
  text "TOP" at 12563.46,3867.6 h60
  text "X" at 12956.46,3867.6 h60
  text "BOTTOM" at 13074.46,3867.6 h60
  text "SILKSCREEN COLOR:" at 11488.68,3712.41 h60
  text "X" at 12445.46,3712.41 h60
  text "WHITE" at 12563.46,3712.41 h60
  text "OTHER" at 13074.46,3712.41 h60
  text "GREEN" at 12694.46,3568.96 h60
  text "X" at 13168.46,3568.96 h60
  text "OTHER" at 13312.46,3568.96 h60
  text "RED" at 13690,3567.96 h60
  text "SOLDER RESIST COLOR:" at 11488.68,3562.1 h60
  text "X" at 12576.46,3414.71 h60
  text "MATTE" at 12694.46,3414.71 h60
  text "SEMI-GLOSS" at 13312,3414.07 h60
  text "IMMERSION GOLD (ENIG)" at 12394.46,3241.94 h60
  text "ENEPIG" at 13732,3234.72 h60
  text "SURFACE FINISH:" at 11333.46,3233.72 h60
  text "X" at 12216.46,3233.72 h60
  text "Top Layer contains 90ohm +/-10% differential pair for USB (D_N/D_P" at 7135,3160 h60
  text "IMM. TIN/SILVER OR EQUIV" at 11663,3096.4 h60
  text "OTHER" at 13094.46,3092.47 h60
  text "and OTGD_N/OTGD_P) using 9mil traces with 7mil spacing" at 7135,3070 h60
  text "Top Layer contains 100ohm +/-10% differential pair for Ethernet using" at 7135,2955 h60
  text "ARRAY/PANEL:" at 11333.46,2937.09 h60
  text "CUT AND TRIM PER M1 BOARD OUTLINE" at 12394.46,2928.87 h60
  text "9mil traces with 10mil spacing" at 7135,2870 h60
  text "N.C. ROUTE" at 12394.46,2792.9 h60
  text "X" at 13082.46,2792.9 h60
  text "V. SCORE" at 13260.46,2792.9 h60
  text "CERTIFICATION:" at 11333.46,2663.77 h60
  text "MATERIALS AND WORKMANSHIP FOR ALL PCBS" at 12058.46,2663.77 h60
  text "TO MEET OR EXCEED THE REQUIREMENTS OF:" at 12058.46,2569.71 h60
  text "X" at 11695.97,2441.08 h60
  text "ANSI IPC-A-600F CLASS ->" at 11823.96,2441.08 h60
  text "X" at 13471.97,2441.08 h60
  text "2" at 13581.96,2441.08 h60
  text "1" at 13266.96,2439.58 h60
  text "3" at 13935.96,2439.58 h60
  text "X" at 12507.97,2293.39 h60
  text "RoHS" at 12635.96,2293.39 h60
  text "OTHER" at 13280.36,2293.39 h60
  text "PER ORDER" at 13677.42,2293.39 h60
  text "ALL BOARDS MUST MEET OR EXCEED UL94-V0 REQUIREMENTS." at 11361,2139.57 h60
  text "PCB MUST BEAR THE UL94V-0 UL REGISTERED MATERIAL ID NUMBER" at 11361,2023.5 h60
  text "ADDITIONAL REQUIREMENTS:" at 11333.46,1854.08 h60
  text "MICROSECTION:" at 11408.23,1746.95 h60
  text "YES" at 12313.96,1746.95 h60
  text "REQUIRED" at 13175.46,1602.62 h60
  text "BARE BOARD ELEC. TEST:" at 11408.23,1599.76 h60
  text "NONE" at 12713.96,1599.76 h60
  text "X" at 13057.46,1599.76 h60
  text "PER ORDER" at 13767.46,1599.76 h60
  text "XX MIL VIAS REQUIRE NON-CONDUCTIVE FILL AND PLANARIZE" at 11576.38,1394.82 h59
  text "XX MIL VIAS REQUIRE CONDUCTIVE FILL AND PLANARIZE" at 11584.38,1290.84 h60
  text "OUTER XX MIL TRACES REQUIRE 50 OHM SINGLE-ENDED IMPEDANCE" at 11583.39,1127.46 h58
  text "LAYER 2 & 3 (INNER LAYERS) XX MIL WIDE, XX MIL SPACE / TRACES REQUIRE 100 OHM DIFFERENTIAL IMPEDANCE" at 11575.39,891.74 h60
  text ".Layer_Name" at 577,-858.49 h60
M11 Gerber Information:
  lines w10: -292,-930.17 6308,-930.17 ; -292,-726.83 6310,-726.83 ; -292,-523.5 -292,-1133.5 3713,-1133.5 6310,-1133.5 6310,-523.5 -291.5,-523.5 -291.5,-1133.5 1284,-1133.5 ; 2173,-1133.5 2173,-523.5 ; 3440,-726.83 3440,-523.5 ; 4280,-726.83 4280,-523.5 ; 4902,-1140 4902,-937.17
  text "ALL ARTWORK VIEWED FROM TOP SIDE" at -228.5,-655.67 h60
  text "BOARD #:" at 2248,-655.67 h60
  text ".PRJ_Number" at 2793.5,-655.67 h60
  text "REV:" at 3638,-655.67 h60
  text ".PCB_Rev" at 3929.5,-655.67 h60
  text "SVN REV:" at 4476,-655.67 h60
  text ".VersionControl_RevNumber" at 4982,-655.67 h60
  text "LAYER NAME =" at -228.5,-858.49 h60
  text "TID #:" at 2248,-859 h60
  text ".TID" at 2793.5,-859 h60
  text "PLOT NAME =" at -228.5,-1064.34 h60
  text ".plot_File_Name" at 577,-1064.34 h60
  text "GENERATED    :" at 2250,-1064.34 h60
  text ".Print_Date" at 3119.5,-1064.34 h60
  text ".Print_Time" at 3848.5,-1064.34 h60
  text "TEXAS INSTRUMENTS" at 5113,-1064.34 h60
M12 Stackup:
  drawing of 399 lines, arcs and shapes, not listed
  text "Layer" at 6680.09,7527.5 h60
  text "Name" at 7090,7527.5 h60
  text "Material" at 8029.74,7527.5 h60
  text "Thickness" at 8889.51,7527.5 h60
  text "Constant" at 9539.34,7527.5 h60
  text "Board Layer Stack" at 10109.2,7527.5 h60
  text "1" at 6680.09,7407.5 h60
  text "Top Overlay" at 7090,7407.5 h60
  text "2" at 6680.09,7287.5 h60
  text "Top Solder" at 7090,7287.5 h60
  text "Solder Resist" at 8029.74,7287.5 h60
  text "0.80mil" at 8889.51,7287.5 h60
  text "3.5" at 9539.34,7287.5 h60
  text "3" at 6680.09,7167.5 h60
  text "Top Layer" at 7090,7167.5 h60
  text "Copper" at 8029.74,7167.5 h60
  text "1.90mil" at 8889.51,7167.5 h60
  text "4" at 6680.09,7047.5 h60
  text "Dielectric 1" at 7090,7047.5 h60
  text "FR-4 or VT47" at 8029.74,7047.5 h60
  text "7.70mil" at 8889.51,7047.5 h60
  text "4.2" at 9539.34,7047.5 h60
  text "5" at 6680.09,6927.5 h60
  text "Signal Layer 1" at 7090,6927.5 h60
  text "Copper" at 8029.74,6927.5 h60
  text "1.20mil" at 8889.51,6927.5 h60
  text "6" at 6680.09,6807.5 h60
  text "Dielectric 2" at 7090,6807.5 h60
  text "FR-4 or VT47" at 8029.74,6807.5 h60
  text "14.00mil" at 8889.51,6807.5 h60
  text "4.2" at 9539.34,6807.5 h60
  text "7" at 6680.09,6687.5 h60
  text "Signal Layer 2" at 7090,6687.5 h60
  text "Copper" at 8029.74,6687.5 h60
  text "1.20mil" at 8889.51,6687.5 h60
  text "8" at 6680.09,6567.5 h60
  text "Dielectric 3" at 7090,6567.5 h60
  text "FR-4 or VT47" at 8029.74,6567.5 h60
  text "8.40mil" at 8889.51,6567.5 h60
  text "4.2" at 9539.34,6567.5 h60
  text "9" at 6680.09,6447.5 h60
  text "Signal Layer 3" at 7090,6447.5 h60
  text "Copper" at 8029.74,6447.5 h60
  text "1.20mil" at 8889.51,6447.5 h60
  text "10" at 6680.09,6327.5 h60
  text "Dielectric 4" at 7090,6327.5 h60
  text "FR-4 or VT47" at 8029.74,6327.5 h60
  text "14.00mil" at 8889.51,6327.5 h60
  text "4.2" at 9539.34,6327.5 h60
  text "11" at 6680.09,6207.5 h60
  text "Signal Layer 4" at 7090,6207.5 h60
  text "Copper" at 8029.74,6207.5 h60
  text "1.20mil" at 8889.51,6207.5 h60
  text "12" at 6680.09,6087.5 h60
  text "Dielectric 5" at 7090,6087.5 h60
  text "FR-4 or VT47" at 8029.74,6087.5 h60
  text "7.70mil" at 8889.51,6087.5 h60
  text "4.2" at 9539.34,6087.5 h60
  text "13" at 6680.09,5967.5 h60
  text "Bottom Layer" at 7090,5967.5 h60
  text "Copper" at 8029.74,5967.5 h60
  text "1.90mil" at 8889.51,5967.5 h60
  text "14" at 6680.09,5847.5 h60
  text "Bottom Solder" at 7090,5847.5 h60
  text "Solder Resist" at 8029.74,5847.5 h60
  text "0.80mil" at 8889.51,5847.5 h60
  text "3.5" at 9539.34,5847.5 h60
  text "15" at 6680.09,5727.5 h60
  text "Bottom Overlay" at 7090,5727.5 h60
  text ".Layer_Name" at 577,-858.49 h60
M13 Component Bodies Top:
  text ".Layer_Name" at 577,-858.49 h60
M14 Component Bodies Bottom:
  text ".Layer_Name" at 577,-858.49 h60
M15 Courtyards Top:
  text ".Layer_Name" at 577,-858.49 h60
M16 Courtyards Bottom:
  text ".Layer_Name" at 577,-858.49 h60
Drill Drawing:
  drawing of 160 lines, arcs and shapes, not listed
  text "Symbol" at 7980.42,5418.46 h72
  text "Quantity" at 8280.57,5418.46 h72
  text "Finished Hole Size" at 8612.26,5418.46 h72
  text "Plated" at 9248.12,5418.46 h72
  text "Hole Type" at 9506.92,5418.46 h72
  text "Drill Layer Pair" at 9881.67,5418.46 h72
  text "Hole Tolerance" at 10604.21,5418.46 h72
  text "2" at 8280.57,5294.43 h60
  text "125.00mil (3.175mm)" at 8612.26,5294.43 h60
  text "NPTH" at 9248.12,5294.43 h60
  text "Round" at 9506.92,5294.43 h60
  text "Top Layer - Bottom Layer" at 9881.67,5294.43 h60
  text "2" at 8280.57,5170.4 h60
  text "127.95mil (3.250mm)" at 8612.26,5170.4 h60
  text "NPTH" at 9248.12,5170.4 h60
  text "Round" at 9506.92,5170.4 h60
  text "Top Layer - Bottom Layer" at 9881.67,5170.4 h60
  text "2" at 8280.57,5046.38 h60
  text "7.87mil (0.200mm)" at 8612.26,5046.38 h60
  text "PTH" at 9248.12,5046.38 h60
  text "Round" at 9506.92,5046.38 h60
  text "Top Layer - Bottom Layer" at 9881.67,5046.38 h60
  text "95" at 8280.57,4922.35 h60
  text "8.00mil (0.203mm)" at 8612.26,4922.35 h60
  text "PTH" at 9248.12,4922.35 h60
  text "Round" at 9506.92,4922.35 h60
  text "Top Layer - Bottom Layer" at 9881.67,4922.35 h60
  text "524" at 8280.57,4798.32 h60
  text "12.00mil (0.305mm)" at 8612.26,4798.32 h60
  text "PTH" at 9248.12,4798.32 h60
  text "Round" at 9506.92,4798.32 h60
  text "Top Layer - Bottom Layer" at 9881.67,4798.32 h60
  text "A" at 7955.17,4788.33 h55.12
  text "10" at 8280.57,4674.3 h60
  text "27.95mil (0.710mm)" at 8612.26,4674.3 h60
  text "PTH" at 9248.12,4674.3 h60
  text "Round" at 9506.92,4674.3 h60
  text "Top Layer - Bottom Layer" at 9881.67,4674.3 h60
  text "20" at 8280.57,4550.27 h60
  text "33.47mil (0.850mm)" at 8612.26,4550.27 h60
  text "PTH" at 9248.12,4550.27 h60
  text "Round" at 9506.92,4550.27 h60
  text "Top Layer - Bottom Layer" at 9881.67,4550.27 h60
  text "8" at 8280.57,4426.24 h60
  text "35.04mil (0.890mm)" at 8612.26,4426.24 h60
  text "PTH" at 9248.12,4426.24 h60
  text "Round" at 9506.92,4426.24 h60
  text "Top Layer - Bottom Layer" at 9881.67,4426.24 h60
  text "6" at 8280.57,4302.21 h60
  text "39.37mil (1.000mm)" at 8612.26,4302.21 h60
  text "PTH" at 9248.12,4302.21 h60
  text "Round" at 9506.92,4302.21 h60
  text "Top Layer - Bottom Layer" at 9881.67,4302.21 h60
  text "+/-1.97mil" at 10604.21,4302.21 h60
  text "7" at 8280.57,4178.19 h60
  text "39.37mil (1.000mm)" at 8612.26,4178.19 h60
  text "PTH" at 9248.12,4178.19 h60
  text "Round" at 9506.92,4178.19 h60
  text "Top Layer - Bottom Layer" at 9881.67,4178.19 h60
  text "110" at 8280.57,4054.16 h60
  text "40.00mil (1.016mm)" at 8612.26,4054.16 h60
  text "PTH" at 9248.12,4054.16 h60
  text "Round" at 9506.92,4054.16 h60
  text "Top Layer - Bottom Layer" at 9881.67,4054.16 h60
  text "148" at 8280.57,3930.13 h60
  text "40.16mil (1.020mm)" at 8612.26,3930.13 h60
  text "PTH" at 9248.12,3930.13 h60
  text "Round" at 9506.92,3930.13 h60
  text "Top Layer - Bottom Layer" at 9881.67,3930.13 h60
  text "2" at 8280.57,3806.11 h60
  text "62.99mil (1.600mm)" at 8612.26,3806.11 h60
  text "PTH" at 9248.12,3806.11 h60
  text "Round" at 9506.92,3806.11 h60
  text "Top Layer - Bottom Layer" at 9881.67,3806.11 h60
  text "2" at 8280.57,3682.08 h60
  text "25.59mil (0.650mm)" at 8612.26,3682.08 h60
  text "PTH" at 9248.12,3682.08 h60
  text "Slot" at 9506.92,3682.08 h60
  text "Top Layer - Bottom Layer" at 9881.67,3682.08 h60
  text "2" at 8280.57,3558.05 h60
  text "32.48mil (0.825mm)" at 8612.26,3558.05 h60
  text "PTH" at 9248.12,3558.05 h60
  text "Slot" at 9506.92,3558.05 h60
  text "Top Layer - Bottom Layer" at 9881.67,3558.05 h60
  text "940 Total" at 8280.57,3434.03 h60
  text "Slot definitions :" at 7980.42,3347.21 h60
  text "Routed Path Length" at 8429.86,3347.21 h60
  text "= Calculated from tool start centre position to tool end centre position." at 8968.21,3347.21 h60
  text "Hole Length" at 8429.86,3297.6 h60
  text "= Routed Path Length + Tool Size = Slot length as defined in the PCB layout" at 8768.91,3297.6 h60
  text ".Layer_Name" at 577,-858.49 h60
M17 Embedded Cavity:
  text ".Layer_Name" at 577,-858.49 h60
M18 Embedded Assembly:
  text ".Layer_Name" at 577,-858.49 h60
M19 Embedded Keepout:
  text ".Layer_Name" at 577,-858.49 h60

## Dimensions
0,0 to 0,6000 on M2 Board Dimensions
0,0 to 4000,0 on M2 Board Dimensions
0,-400 to 1000,-400 on M2 Board Dimensions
